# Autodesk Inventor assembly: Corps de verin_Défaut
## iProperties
Shininess: 64.0
Length Units: 11269
Angle Units: 11279
Time Units: 11290
Mass Units: 11283
Length Display Precision: 3
Angle Display Precision: 2
Compacted: True
Created: 2006-11
Part Number: Corps de verin_Défaut
Document SubType Name: Assembly
Designer: profs_sti
Density: 0.0
Volumn: 0.0
Area: 0.0
PropertySet Name: Model Information
Control State: 0
Master: False
Checked Out: False
Author: profs_sti
